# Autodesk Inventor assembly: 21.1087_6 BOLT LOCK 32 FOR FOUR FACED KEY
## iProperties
Created: 2007-03
Part Number: 21.1087_6 BOLT LOCK 32 FOR FOUR FACED KEY
Document SubType Name: Assembly
Designer: Andy Moles
Author: Andy Moles
